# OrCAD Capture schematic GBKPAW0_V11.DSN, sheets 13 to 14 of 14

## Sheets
13 PAGE06:KEY&LED&RESET: size B
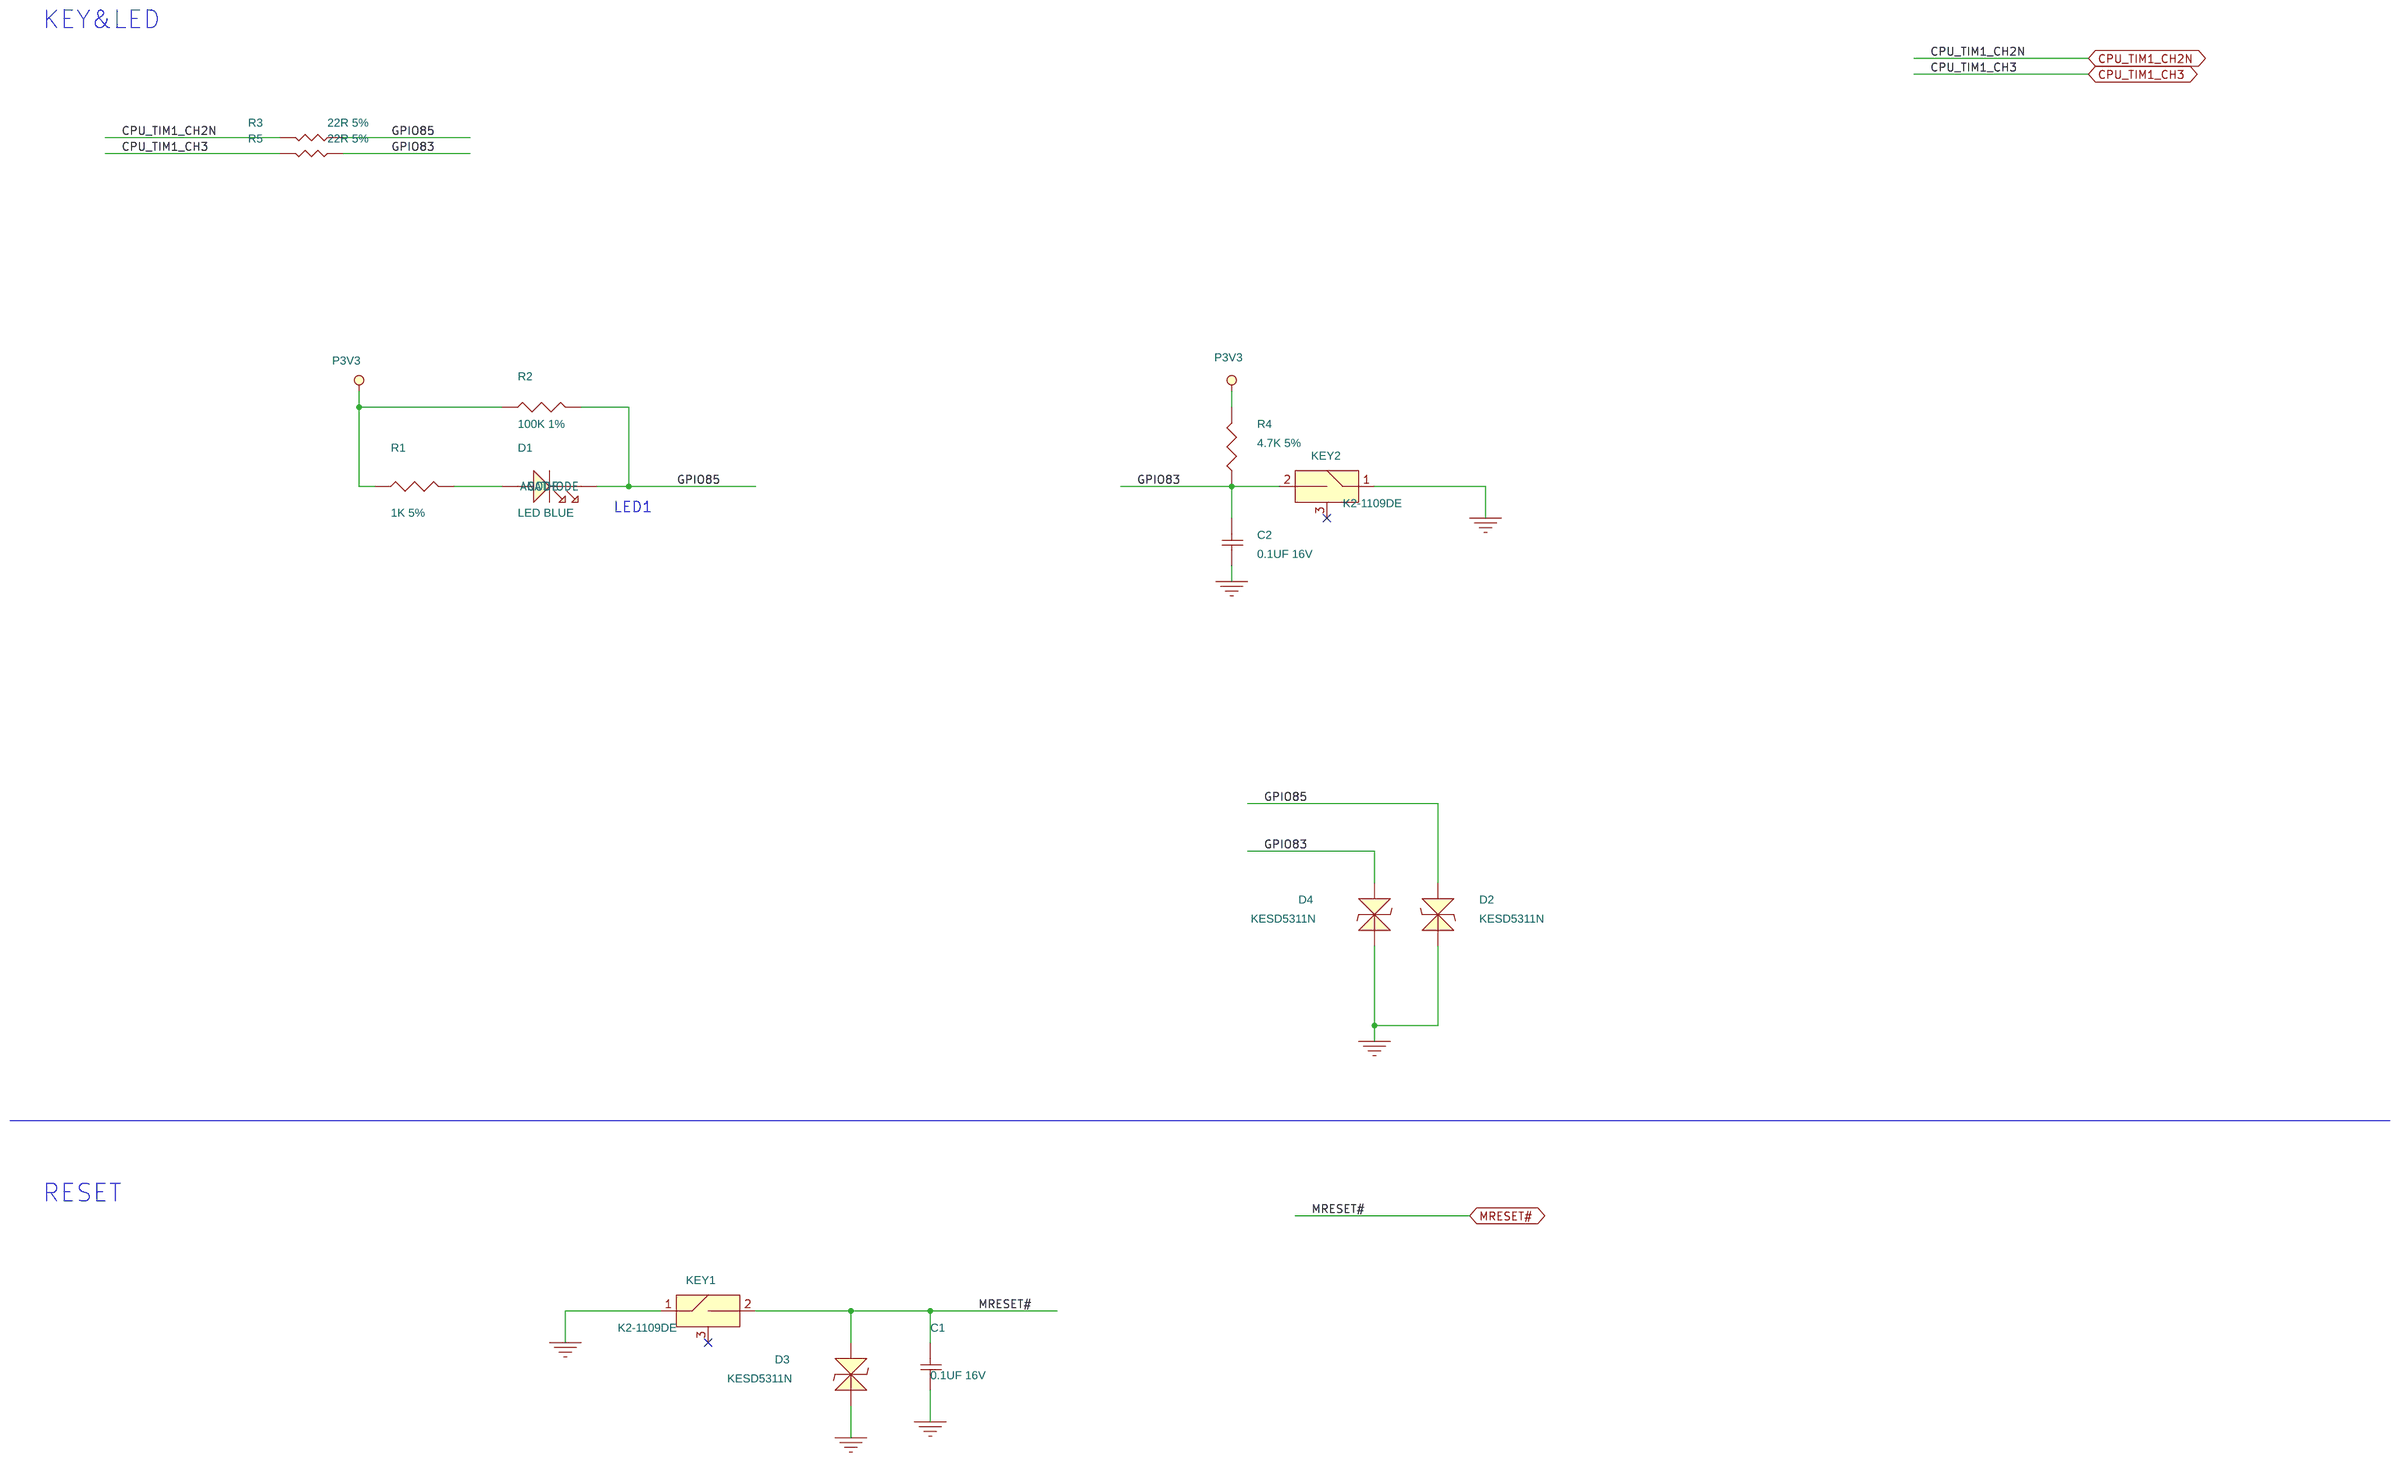
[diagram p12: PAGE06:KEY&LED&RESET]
14 PAGE14:REVISION HISTORY
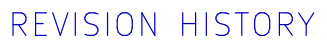
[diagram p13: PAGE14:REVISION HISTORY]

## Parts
C1  0.1UF 16V  [C0402]
C2  0.1UF 16V  [C0402]
D1  LED BLUE  [LEDS_19_21SYGC]
D2  KESD5311N  [ESDPSA-0402]
D3  KESD5311N  [ESDPSA-0402]
D4  KESD5311N  [ESDPSA-0402]
KEY1  K2-1109DE  [SW3_3050]
KEY2  K2-1109DE  [SW3_3050]
R1  1K 5%  [R0402]
R2  100K 1%  [R0402]
R3  22R 5%  [R0402]
R4  4.7K 5%  [R0402]
R5  22R 5%  [R0402]

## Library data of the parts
C1 = C: CAP,MLCC,0.1UF,16V,10%,C0402/SMT,X7R,ROHS; Component Name: 0.1UF 16V C0402 YAGEO CC0402KRX7R7BB104; Manufacturer: YAGEO; Manufacturer PN: CC0402KRX7R7BB104; Option: I; Package type: SMT; Part Number: C111042XK62YG1; Part Type: 陶瓷电容; ROHS: Y; Remark: Reserved; Status: 商业级; Datasheet: Z:\lib\Datasheet\RC\YAGEO-C.pdf
C2 = C: CAP,MLCC,0.1UF,16V,10%,C0402/SMT,X7R,ROHS; Component Name: 0.1UF 16V C0402 YAGEO CC0402KRX7R7BB104; ID: 22; Manufacturer: YAGEO; Manufacturer PN: CC0402KRX7R7BB104; Option: I; Package type: SMT; Part Number: C111042XK62YG1; Part Type: 陶瓷电容; ROHS: Y; Remark: Reserved; SIGNAL_MODEL: C_C0402_0.1UF_16V_0.1UF_16V; Status: 商业级; Datasheet: C:\Cadence\lib\Datasheet\RC\YAGEO-C.pdf
D1 = LED_0: LED BLUE,LED0603/SMT,Vr=5V,If=5mA,ROHS; Component Name: EVERLIGHT LED Red 17_21SURC/S530-A3/TR8; ID: 45; Manufacturer: 国星光电; Manufacturer PN: NCD0603B1; Option: I; Package type: SMT; Part Type: LED蓝灯色; ROHS: Y; Remark: Reserved; Status: 商业级; Datasheet: D:\lib_ls\Datasheet\Diodes-Transistor\17_21SURC_S530-A3_TR8.pdf
D2-D4 = ESD_DIODE_0: ESD Protection devices,ESDPSA-0402/SMT,ESD protection for high speed data lines,ROHS; Component Name: KUU KESD5311N; ID: 160; Manufacturer: KUU; Option: I; Package type: SMT; Part Number: DJ1ESDPSA12SKU-GZ; Part Type: 瞬态电压抑制二极管; ROHS: Y; Remark: Reserved; Status: 商业级; Datasheet: D:\lib_ls\Datasheet\KESD5311N.PDF
KEY1 KEY2 = K2-1109DE: 4.5x4.5mm 侧立 按键开关,按键长度2MM; Manufacturer: HRO; Manufacturer PN: K2-1109DE-D4SW-01; Remark: 注意按键长度2MM
R1 = R: RESISITOR, 1K Ohm, 5%, R0402/SMT, 1/16W, ROHS; Component Name: 1K 5% R0402 YAGEO RC0402JR-071KL; ID: 18; Manufacturer: YAGEO; Manufacturer PN: RC0402JR-071KL; Option: I; Package type: SMT; Part Number: R1101022JC2YG1; Part Type: 电阻; ROHS: Y; Remark: Reserved; Status: 商业级; Datasheet: D:\lib_ls\Datasheet\RC\YAGEO-R.pdf
R2 = R: RESISTOR, 100K Ohm, 1%, R0402/SMT, 1/16W, ROHS; Component Name: 100K 1% R0402 YAGEO RC0402FR-07100KL; ID: 193; Manufacturer: YAGEO; Manufacturer PN: RC0402FR-07100KL; Option: I; Package type: SMT; Part Number: R1110032FC2YG1; Part Type: 电阻; ROHS: Y; Remark: Reserved; Status: 商业级; Datasheet: D:\lib_ls\Datasheet\RC\YAGEO-R.pdf
R3 R5 = R_v5: RESISITOR,22R Ohm,5%,R0402/SMT, 1/16W,ROHS; Component Name: 22R 5% R0402 FH  RC-02W220JT; ID: 1,186; Manufacturer: FH(风华); Manufacturer PN: RC-02W220JT; Option: I; Package type: SMT; Part Number: RJ102202JC2FH1-GZ; Part Type: 电阻; ROHS: Y; Remark: Reserved; Status: 商业级; Datasheet: D:\lib_ls\Datasheet\RC\FH-R.pdf
R4 = R: RESISITOR, 4.7K Ohm, 5%, R0402/SMT, 1/16W, ROHS; Component Name: 4.7K 5% R0402 FH RC-02W472JT; ID: 1,195; Manufacturer: FH(风华); Manufacturer PN: RC-02W472JT; Option: I; Package type: SMT; Part Number: R1104722JC2FH1-GZ; Part Type: 电阻; ROHS: Y; Remark: Reserved; Status: 商业级; Datasheet: D:\lib_ls\Datasheet\RC\FH-R.pdf

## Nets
GND: C1.2 C2.2 D2.1 D3.1 D4.1 KEY1.1 KEY2.1 ; also on sheet 1 2 3 4 6 7 8 9 10
P3V3: R1.1 R2.1 R4.2 ; also on sheet 1 2 3 4 7 9 10
CPU_TIM1_CH2N: R3.2 ; also on sheet 8
CPU_TIM1_CH3: R5.2 ; also on sheet 8
GPIO83: C2.1 D4.2 KEY2.2 R4.1 R5.1
GPIO85: D1.C(CATHODE) D2.2 R2.2 R3.1
MRESET#: C1.1 D3.2 KEY1.2 ; also on sheet 8 10
N21863620: D1.A(ANODE) R1.2

Not connected (* = marked no-connect by the designer): KEY1 3*; KEY2 3*

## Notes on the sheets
sheet 13
- KEY&LED
- LED1
- RESET
sheet 14
- REVISION HISTORY
